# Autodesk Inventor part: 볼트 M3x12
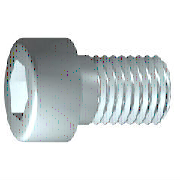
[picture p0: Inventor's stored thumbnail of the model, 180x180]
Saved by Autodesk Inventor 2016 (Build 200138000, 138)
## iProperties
IsCustomPart: 0
Created: 2012-02
Part Number: 볼트 M3x12
Material: 강철, 연강
Description: 6각머리 태핑 나사
Document SubType Name: Modeling
Standard: KS B 1003
Designer: mduedu
Standards Organization: KS
Language: ko-KR
Size Designation: M 3 x 12
Categories: <MemberInstance><Categories><Category DisplayName="조임쇠" InternalName="e4da775c-781d-43d5-af7c-5136215cf5a6" Mnemonic="FSTN"><Category DisplayName="볼트" InternalN
Density: 1 g/cm^3
Appearance: 강철
Author: mduedu
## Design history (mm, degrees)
sketch "스케치1"
  geometry: L1 (-0.867, 0)-(12, 0); L2 (12, 0)-(12, 1.5); L3 (12, 1.5)-(1.25, 1.5); L4 (1.25, 1.5)-(0.943, 1.5); L5 (0.943, 1.5)-(0, 1.5); L6 (0, 1.5)-(0, 2.75); L7 (0, 2.75)-(-3, 2.75); L8 (-3, 2.75)-(-3, 1.443); L9 (-3, 1.443)-(-1.7, 1.443); L10 (-1.7, 1.443)-(-0.867, 0); L11 (-6, 0)-(15, 0) reference; L12 (0, -0.55)-(0, 3.3) reference; L13 (1.25, 1.5)-(0, 1.5)
  constraints: 22 end point, 6 parallel, 2 collinear, 2 perpendicular, 1 horizontal, 1 point on line
  dimensions: "d1" = 10.75 distance from line of L3.end L2 (= GEL); "d2" = 0.30683 distance of L4.end L3.end (computed from GAL); "d3" = 3 distance between parallel lines of L8 L6 (= KOH); "d4" = 1.3 distance of L8.end L9.end (= INTI); "d5" = 60 deg angle of L10 L1; "d6" = 3 diameter of L3 L1 (= GD); "d7" = 3 diameter of L5 L1 (= BDM); "d8" = 2.88675 diameter of L9 L1 (= 1.1547 x SW); "d9" = 5.5 diameter of L7 L1 (= KOD); "d26" = 12 distance between parallel lines of L12 L2 (= NLG)
revolve "본체" sketch "스케치1" stored, may be unused: angle "d10" = 90 deg
sketch "스케치2"
  geometry: L1 (0, -3.85)-(0, 3.85) reference; L2 (-3.85, 0)-(3.85, 0) reference; L3 (1.443, 0)-(0.722, -1.25); L4 (0.722, -1.25)-(-0.722, -1.25); L5 (-0.722, -1.25)-(-1.443, 0); L6 (-1.443, 0)-(-0.722, 1.25); L7 (-0.722, 1.25)-(0.722, 1.25); L8 (0.722, 1.25)-(1.443, 0); 2 further points
  constraints: 12 end point, 1 coincident, 1 horizontal alignment, 1 point on line, 12 other
extrude "슬롯" join sketch "스케치2" stored distance "d11" = 10; taper "d12" = 0 deg
workplane "Work Plane1"
fillet "Fillet2" dims "d30" = 0.1 (= R)
body "Solid1"
fillet "모깎기1" dims "d17" = 0.3 (= RR)
feature "스레드" dims "d13" = 10.75 (= GEL), "d14" = 0
chamfer "모따기1" distance "d15" = 0.30673 (= -0.5 x SPD + 0.5 x GD); stored, may be unused: second distance "d16" = 0.30673 (= GUL), angle "d27" = 45 deg
other parameters: "GD" = 3 (= NND) [user parameter; used in 2 equation terms], "NLG" = 12 [user parameter; used in 1 equation term], "GEL" = 10.75 [user parameter; used in 2 equation terms], "KOD" = 5.5 [user parameter; used in 1 equation term], "KOH" = 3 [user parameter; used in 1 equation term], "INTI" = 1.3 [user parameter; used in 1 equation term], "GAL" = 0.30673 (= 0.61345 x PTC) [user parameter; used in 1 equation term], "GUL" = 0.30673 (= 0.61345 x PTC) [user parameter; used in 1 equation term], "BDM" = 3 (= NND) [user parameter; used in 1 equation term], "SW" = 2.5 [user parameter; used in 2 equation terms], "RR" = 0.3 [user parameter; used in 1 equation term], "SPD" = 2.38655 (= NND - 1.2269 x PTC) [user parameter; used in 1 equation term], "d19" = 0, "d28" = 0, "d29" = 0, "R" = 0.1 [user parameter; used in 1 equation term], "PHH" = 0.1 [user parameter], "GD1" = 2.38655 (= THREADDIA - 1.2269 x PTC) [user parameter], "THREADDIA" = 3 [user parameter; used in 1 equation term], "FAWI" = 45 deg [user parameter], "PTC" = 0.5 [user parameter; used in 5 equation terms], "NND" = 3 [user parameter; used in 3 equation terms], "TOA" = 30 deg [user parameter], "E0" = 2.8875 (= 1.155 x SW) [user parameter]
